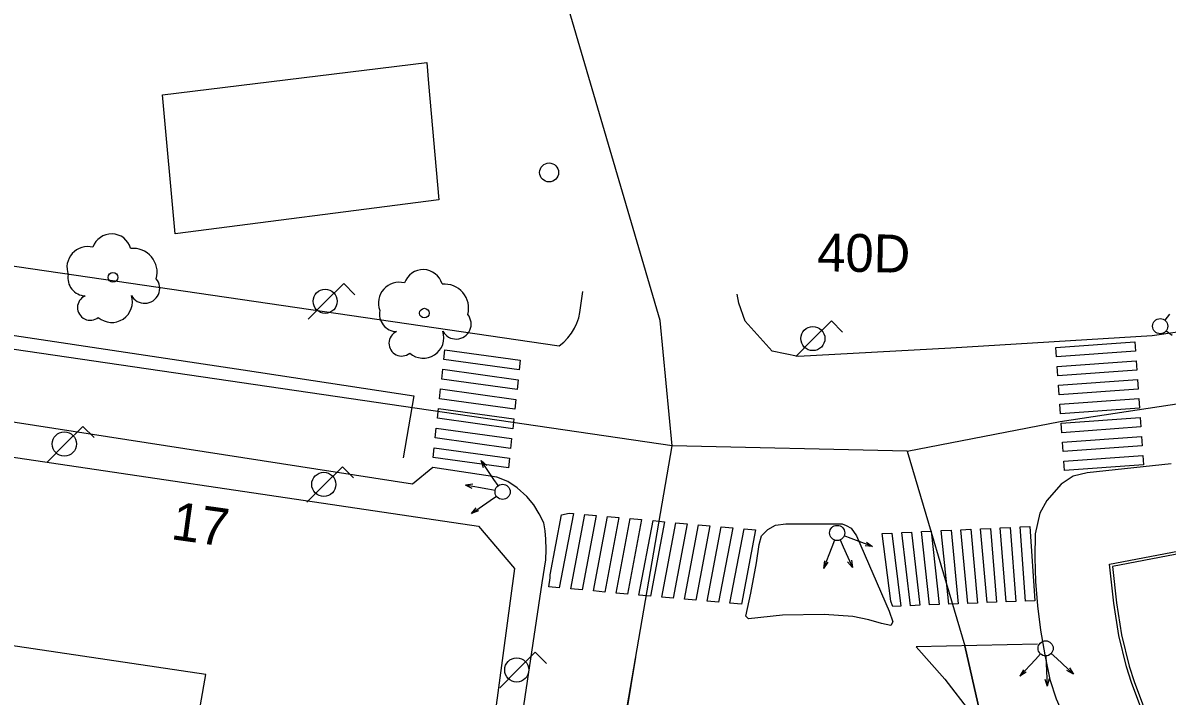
# Model space of a CAD drawing. Extents: x 282771 to 285132, y 4823109 to 4825496.
# Drawn here: x 283576.8 to 283637.2, y 4824263.2 to 4824298.7 of the extents above; entities that cross this region are included whole.
import ezdxf

# ---------------------------------------------------------------- set-up
doc = ezdxf.new("R2010")
doc.units = 0
for name, color, linetype in [('ACERA-BORDILLO', 7, 'Continuous'), ('ACERA-INTERIOR', 7, 'Continuous'), ('ARBOL', 7, 'Continuous'), ('BORDILLO', 7, 'Continuous'), ('CALLE-EJE', 7, 'Continuous'), ('EDIFICIO', 7, 'Continuous'), ('FAROLA', 7, 'Continuous'), ('INTERIOR-EDIFICIO', 7, 'Continuous'), ('NUM-LOCAL', 7, 'Continuous'), ('NUM-PORTAL', 7, 'Continuous'), ('PASO-PEATONES', 7, 'Continuous'), ('POSTE', 7, 'Continuous'), ('SEMAFORO', 7, 'Continuous'), ('SENAL-VIARIA', 7, 'Continuous'), ('ZONA-VERDE', 7, 'Continuous')]:
    doc.layers.add(name, color=color, linetype=linetype)

msp = doc.modelspace()

# ---------------------------------------------------------------- linework, layer by layer
at = {"layer": 'ACERA-BORDILLO'}
for points in [[(283355.136, 4824321.191), (283355.199, 4824319.985), (283355.415, 4824319.703), (283355.66, 4824319.449), (283355.93, 4824319.229), (283356.217, 4824319.046), (283415.472, 4824309.558), (283420.923, 4824311.755), (283441.34, 4824308.636), (283445.326, 4824305.446), (283489.55, 4824298.604), (283605.089, 4824281.705), (283605.336, 4824281.899), (283605.558, 4824282.121), (283605.751, 4824282.366), (283605.91, 4824282.628), (283606.035, 4824282.902), (283606.126, 4824283.18), (283606.183, 4824283.457), (283606.353, 4824284.571)], [(283645.993, 4824283.627), (283636.378, 4824282.232), (283625.768, 4824281.577), (283617.713, 4824281.142), (283616.333, 4824281.417), (283614.913, 4824283.001), (283614.583, 4824283.961), (283614.496, 4824284.425)], [(283600.686, 4824245.623), (283604.195, 4824269.193), (283604.387, 4824270.405), (283604.402, 4824270.967), (283604.387, 4824271.499), (283604.357, 4824271.943), (283604.283, 4824272.357), (283604.047, 4824272.844), (283603.766, 4824273.318), (283603.396, 4824273.761), (283602.879, 4824274.205), (283602.391, 4824274.545), (283601.815, 4824274.781), (283598.429, 4824275.284), (283597.35, 4824274.397), (283540.343, 4824283.26)], [(283637.388, 4824275.487), (283632.963, 4824275.002), (283632.223, 4824274.832), (283631.583, 4824274.402), (283630.823, 4824273.552), (283630.463, 4824272.882), (283630.203, 4824271.782), (283630.193, 4824270.537), (283630.237, 4824269.274), (283630.337, 4824267.995), (283630.495, 4824266.705), (283630.713, 4824265.406), (283630.992, 4824264.104), (283631.322, 4824263.084), (283632.369, 4824260.665), (283633.767, 4824257.907), (283635.164, 4824255.541), (283637.018, 4824253.203), (283638.926, 4824251.428)]]:
    msp.add_lwpolyline(points, dxfattribs=at)
at = {"layer": 'ACERA-INTERIOR'}
msp.add_lwpolyline([(283637.478, 4824259.307), (283636.623, 4824260.792), (283636.223, 4824261.552), (283635.893, 4824262.342), (283635.293, 4824263.947), (283635.023, 4824264.762), (283634.623, 4824266.422), (283634.353, 4824268.122), (283634.128, 4824270.19), (283645.777, 4824272.409)], dxfattribs=at)
at = {"layer": 'ARBOL'}
for centre in [(283581.551, 4824285.315), (283597.986, 4824283.428)]:
    msp.add_circle(centre, 0.255, dxfattribs=at)
for centre, radius, start, end in [((283581.481, 4824286.575), 1.038, 15.64228, 161.38435), ((283580.221, 4824285.845), 1.097, 75.4318, 200.55608), ((283582.611, 4824285.575), 1.272, 345.03273, 95.79925), ((283580.111, 4824285.275), 0.935, 168.59898, 268.13236), ((283597.916, 4824284.688), 1.038, 15.64228, 161.38435), ((283583.221, 4824284.745), 0.797, 208.96246, 38.99103), ((283596.656, 4824283.958), 1.097, 75.4318, 200.55608), ((283599.046, 4824283.688), 1.272, 345.03273, 95.79925), ((283580.351, 4824283.725), 0.672, 113.73672, 309.4725), ((283581.491, 4824284.025), 1.086, 228.95447, 17.92796), ((283596.546, 4824283.388), 0.935, 168.59898, 268.13236), ((283599.656, 4824282.858), 0.797, 208.96246, 38.99103), ((283596.786, 4824281.838), 0.672, 113.73672, 309.4725), ((283597.926, 4824282.138), 1.086, 228.95447, 17.92796)]:
    msp.add_arc(centre, radius, start, end, dxfattribs=at)
at = {"layer": 'BORDILLO'}
msp.add_lwpolyline([(283614.942, 4824267.44), (283615.202, 4824268.647), (283615.51, 4824270.257), (283615.652, 4824271.228), (283615.77, 4824271.677), (283616.101, 4824272.009), (283616.503, 4824272.246), (283617.048, 4824272.317), (283618.089, 4824272.317), (283620.029, 4824272.317), (283620.242, 4824272.222), (283620.502, 4824272.08), (283620.786, 4824271.677), (283622.51, 4824267.703), (283622.695, 4824267.139), (283622.604, 4824266.957), (283622.095, 4824267.063), (283621.442, 4824267.253), (283620.597, 4824267.416), (283619.083, 4824267.535), (283616.882, 4824267.488), (283615.084, 4824267.298), (283614.942, 4824267.44)], dxfattribs=at)
at = {"layer": 'CALLE-EJE'}
for points in [[(283623.463, 4824276.152), (283631.536, 4824277.707), (283643.497, 4824279.522), (283655.03, 4824282.192), (283668.593, 4824286.463), (283695.931, 4824296.288), (283808.594, 4824337.616), (283856.649, 4824355.45), (283890.715, 4824367.944), (283918.427, 4824378.463), (283946.139, 4824388.982), (283948.755, 4824389.292), (283951.27, 4824389.061), (283954.039, 4824388.011), (283957.804, 4824384.284), (283969.178, 4824351.877)], [(283611.064, 4824276.435), (283610.423, 4824283.048), (283587.513, 4824361.121)], [(283611.064, 4824276.435), (283480.444, 4824295.551), (283473.554, 4824296.591)], [(283604.299, 4824237.26), (283611.064, 4824276.435)], [(283623.463, 4824276.152), (283611.064, 4824276.435)], [(283623.463, 4824276.152), (283626.508, 4824265.884), (283627.666, 4824260.75), (283629.171, 4824255.454), (283629.95, 4824253.922), (283630.783, 4824252.497), (283631.75, 4824251.315), (283634.141, 4824249.057), (283650.523, 4824235.462)]]:
    msp.add_lwpolyline(points, dxfattribs=at)
at = {"layer": 'EDIFICIO'}
for points in [[(283589.063, 4824295.551), (283598.113, 4824296.661), (283598.203, 4824295.551), (283598.753, 4824289.401), (283584.843, 4824287.621), (283584.173, 4824294.951), (283589.063, 4824295.551)], [(283570.937, 4824276.617), (283600.847, 4824272.182), (283602.74, 4824269.956), (283599.428, 4824245.304), (283596.209, 4824243.552), (283585.953, 4824245.302), (283568.623, 4824247.912)]]:
    msp.add_lwpolyline(points, dxfattribs=at)
at = {"layer": 'FAROLA'}
for p, q in [((283593.729, 4824284.985), (283592.789, 4824284.055)), ((283594.319, 4824284.395), (283593.729, 4824284.985)), ((283592.789, 4824284.055), (283591.859, 4824283.115)), ((283619.461, 4824283.018), (283618.521, 4824282.088)), ((283620.051, 4824282.428), (283619.461, 4824283.018)), ((283618.521, 4824282.088), (283617.591, 4824281.148)), ((283579.967, 4824277.455), (283579.027, 4824276.525)), ((283580.557, 4824276.865), (283579.967, 4824277.455)), ((283579.027, 4824276.525), (283578.097, 4824275.585)), ((283593.657, 4824275.326), (283592.717, 4824274.396)), ((283594.247, 4824274.736), (283593.657, 4824275.326)), ((283592.717, 4824274.396), (283591.787, 4824273.456)), ((283603.837, 4824265.535), (283602.897, 4824264.605)), ((283604.427, 4824264.945), (283603.837, 4824265.535)), ((283602.897, 4824264.605), (283601.967, 4824263.665))]:
    msp.add_line(p, q, dxfattribs=at)
for centre in [(283592.749, 4824284.055), (283618.481, 4824282.088), (283578.987, 4824276.525), (283592.677, 4824274.396), (283602.857, 4824264.605)]:
    msp.add_circle(centre, 0.637, dxfattribs=at)
at = {"layer": 'INTERIOR-EDIFICIO'}
msp.add_lwpolyline([(283576.723, 4824254.772), (283577.501, 4824259.946), (283579.033, 4824257.343), (283585.882, 4824261.169), (283586.449, 4824264.37), (283563.009, 4824267.846)], dxfattribs=at)
at = {"layer": 'PASO-PEATONES'}
for points in [[(283631.343, 4824281.122), (283631.303, 4824281.622), (283635.473, 4824281.921), (283635.513, 4824281.421)], [(283602.983, 4824280.431), (283599.008, 4824280.982), (283599.065, 4824281.5), (283603.039, 4824280.948)], [(283631.413, 4824280.122), (283631.373, 4824280.622), (283635.543, 4824280.921), (283635.583, 4824280.421)], [(283602.871, 4824279.397), (283598.896, 4824279.948), (283598.952, 4824280.465), (283602.927, 4824279.914)], [(283602.758, 4824278.363), (283598.783, 4824278.914), (283598.839, 4824279.431), (283602.814, 4824278.88)], [(283631.483, 4824279.122), (283631.443, 4824279.622), (283635.613, 4824279.921), (283635.653, 4824279.421)], [(283631.553, 4824278.122), (283631.513, 4824278.622), (283635.683, 4824278.922), (283635.723, 4824278.422)], [(283602.645, 4824277.328), (283598.671, 4824277.879), (283598.727, 4824278.397), (283602.702, 4824277.845)], [(283631.623, 4824277.122), (283631.583, 4824277.622), (283635.753, 4824277.922), (283635.793, 4824277.422)], [(283602.533, 4824276.294), (283598.558, 4824276.845), (283598.614, 4824277.362), (283602.589, 4824276.811)], [(283631.693, 4824276.122), (283631.653, 4824276.622), (283635.823, 4824276.922), (283635.863, 4824276.422)], [(283602.42, 4824275.26), (283598.446, 4824275.811), (283598.502, 4824276.328), (283602.477, 4824275.777)], [(283631.763, 4824275.122), (283631.723, 4824275.622), (283635.893, 4824275.922), (283635.933, 4824275.422)], [(283605.103, 4824268.932), (283604.548, 4824268.982), (283604.619, 4824269.47), (283604.623, 4824269.625), (283605.219, 4824272.782), (283605.623, 4824272.88), (283605.845, 4824272.859)], [(283606.304, 4824268.824), (283605.703, 4824268.878), (283606.445, 4824272.805), (283607.045, 4824272.751)], [(283607.504, 4824268.716), (283606.904, 4824268.77), (283607.646, 4824272.697), (283608.246, 4824272.643)], [(283608.705, 4824268.608), (283608.105, 4824268.662), (283608.847, 4824272.589), (283609.447, 4824272.535)], [(283609.906, 4824268.499), (283609.306, 4824268.554), (283610.047, 4824272.481), (283610.648, 4824272.427)], [(283611.107, 4824268.391), (283610.506, 4824268.445), (283611.248, 4824272.373), (283611.849, 4824272.319)], [(283612.308, 4824268.283), (283611.707, 4824268.337), (283612.449, 4824272.265), (283613.049, 4824272.211)], [(283613.508, 4824268.175), (283612.908, 4824268.229), (283613.65, 4824272.157), (283614.25, 4824272.103)], [(283628.682, 4824268.194), (283628.372, 4824272.104), (283628.892, 4824272.124), (283629.182, 4824268.214)], [(283629.692, 4824268.234), (283629.412, 4824272.154), (283629.932, 4824272.174), (283630.192, 4824268.254)], [(283614.709, 4824268.067), (283614.109, 4824268.121), (283614.85, 4824272.049), (283615.451, 4824271.995)], [(283622.587, 4824268.226), (283622.132, 4824271.804), (283622.652, 4824271.824), (283623.122, 4824267.974), (283622.694, 4824267.957), (283622.685, 4824267.979)], [(283623.632, 4824267.994), (283623.172, 4824271.854), (283623.692, 4824271.874), (283624.132, 4824268.014)], [(283624.642, 4824268.034), (283624.212, 4824271.904), (283624.732, 4824271.924), (283625.142, 4824268.054)], [(283625.652, 4824268.074), (283625.252, 4824271.954), (283625.772, 4824271.974), (283626.152, 4824268.094)], [(283626.662, 4824268.114), (283626.292, 4824272.004), (283626.812, 4824272.024), (283627.162, 4824268.134)], [(283627.672, 4824268.154), (283627.332, 4824272.054), (283627.852, 4824272.074), (283628.172, 4824268.174)]]:
    msp.add_lwpolyline(points, close=True, dxfattribs=at)
at = {"layer": 'POSTE'}
msp.add_circle((283604.563, 4824290.851), 0.5, dxfattribs=at)
at = {"layer": 'SEMAFORO'}
for p, q in [((283637.29, 4824283.382), (283637.049, 4824283.063)), ((283637.128, 4824282.503), (283637.448, 4824282.262)), ((283601.657, 4824274.657), (283600.978, 4824275.646)), ((283601.111, 4824275.276), (283600.978, 4824275.646)), ((283601.275, 4824275.389), (283600.978, 4824275.646)), ((283601.884, 4824274.327), (283601.657, 4824274.657)), ((283600.546, 4824274.403), (283600.15, 4824274.361)), ((283601.332, 4824274.142), (283600.15, 4824274.361)), ((283600.505, 4824274.18), (283600.15, 4824274.361)), ((283601.721, 4824274.07), (283601.332, 4824274.142)), ((283600.462, 4824272.865), (283601.451, 4824273.545)), ((283601.451, 4824273.545), (283601.781, 4824273.771)), ((283600.462, 4824272.865), (283600.718, 4824273.163)), ((283600.832, 4824272.998), (283600.462, 4824272.865)), ((283620.51, 4824271.544), (283620.136, 4824271.688)), ((283621.63, 4824271.114), (283620.51, 4824271.544)), ((283619.476, 4824271.085), (283619.045, 4824269.965)), ((283619.619, 4824271.458), (283619.476, 4824271.085)), ((283619.924, 4824271.47), (283620.085, 4824271.108)), ((283620.085, 4824271.108), (283620.573, 4824270.009)), ((283621.63, 4824271.114), (283621.239, 4824271.157)), ((283621.311, 4824271.343), (283621.63, 4824271.114)), ((283619.088, 4824270.355), (283619.045, 4824269.965)), ((283620.314, 4824270.312), (283620.573, 4824270.009)), ((283620.521, 4824270.404), (283620.573, 4824270.009)), ((283619.275, 4824270.284), (283619.045, 4824269.965)), ((283630.221, 4824265.153), (283629.409, 4824264.27)), ((283630.492, 4824265.447), (283630.221, 4824265.153)), ((283630.779, 4824265.346), (283630.796, 4824264.95)), ((283630.796, 4824264.95), (283630.846, 4824263.749)), ((283631.352, 4824265.2), (283631.057, 4824265.471)), ((283632.235, 4824264.388), (283631.352, 4824265.2)), ((283629.593, 4824264.617), (283629.409, 4824264.27)), ((283629.74, 4824264.482), (283629.409, 4824264.27)), ((283632.235, 4824264.388), (283631.888, 4824264.571)), ((283632.023, 4824264.719), (283632.235, 4824264.388)), ((283630.717, 4824264.126), (283630.846, 4824263.749)), ((283630.943, 4824264.136), (283630.846, 4824263.749))]:
    msp.add_line(p, q, dxfattribs=at)
for centre in [(283636.809, 4824282.743), (283602.11, 4824273.998), (283619.763, 4824271.832), (283630.763, 4824265.742)]:
    msp.add_circle(centre, 0.4, dxfattribs=at)
at = {"layer": 'SENAL-VIARIA'}
for points in [[(283469.154, 4824298.338), (283588.417, 4824280.446)], [(283588.417, 4824280.446), (283597.432, 4824279.072), (283596.868, 4824275.796)], [(283630.326, 4824265.965), (283623.931, 4824265.83)], [(283623.931, 4824265.83), (283625.436, 4824264.11), (283626.806, 4824262.363), (283627.666, 4824260.75), (283626.508, 4824265.884)], [(283601.83, 4824219.804), (283602.126, 4824223.272), (283602.609, 4824226.713), (283603.066, 4824230.234), (283607.943, 4824258.022), (283609.138, 4824265.283)]]:
    msp.add_lwpolyline(points, dxfattribs=at)
at = {"layer": 'ZONA-VERDE'}
for points in [[(283645.486, 4824272.201), (283634.292, 4824270.069)], [(283634.292, 4824270.069), (283634.502, 4824268.142), (283634.77, 4824266.451), (283635.167, 4824264.803), (283635.434, 4824263.997), (283636.032, 4824262.397), (283636.359, 4824261.616), (283636.754, 4824260.864), (283637.605, 4824259.387)]]:
    msp.add_lwpolyline(points, dxfattribs=at)

# ---------------------------------------------------------------- texts
at = {"layer": 'NUM-LOCAL'}
msp.add_text('40D', height=2, rotation=358.92004, dxfattribs=at).set_placement((283618.698, 4824285.645))
at = {"layer": 'NUM-PORTAL'}
msp.add_text('17', height=2, rotation=352.02004, dxfattribs=at).set_placement((283584.563, 4824271.512))

doc.saveas('drawing.dxf')
